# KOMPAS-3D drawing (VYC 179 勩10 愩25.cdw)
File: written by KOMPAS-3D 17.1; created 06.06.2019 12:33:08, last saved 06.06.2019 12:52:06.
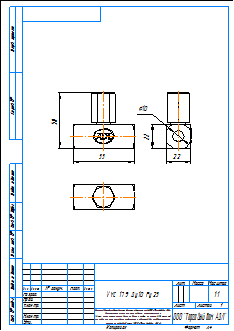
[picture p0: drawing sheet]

Sheet 1: A4, portrait

Title block, sheet 1: name: VYC 179 Ду10 Ру25; material: Внимание! Данный продукт является объектом авторского права ООО «Торговый Дом АДЛ». / Запрещается изменение, копирование, распространение / (в том числе путем копирования на другие сайты и ресурсы в Интернете) / или любое иное использование информации и объектов без предварительного / согласия правообладателя (ООО «Торговый Дом АДЛ»).; sheets: 1; organisation: ООО "Торговый дом АДЛ"; sheet format: A4; stored path: \\adlc.lan\data\АДЛ_ПКД\3D-модели\Поставщики\VYC Industrial\VYC 179\KOMPAS 2D\VYC 179 Ду10 Ру25.cdw

Views: Вид 1, Проекционный вид 2, Проекционный вид 3
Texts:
  user
Dimensions and other numbers on the sheet: 55; 50; 22; 10; 1:1; 1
